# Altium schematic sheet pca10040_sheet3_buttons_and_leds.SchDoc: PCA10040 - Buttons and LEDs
size A4; Revision: 1.1.0; SheetNumber: 3; SheetTotal: 5; DrawnBy: KJP; ProjectNumber: 4397; PCBRevision: 0071KJP; DocumentSize: A4; PCAName: PCA10040; PCBNumber: 400150
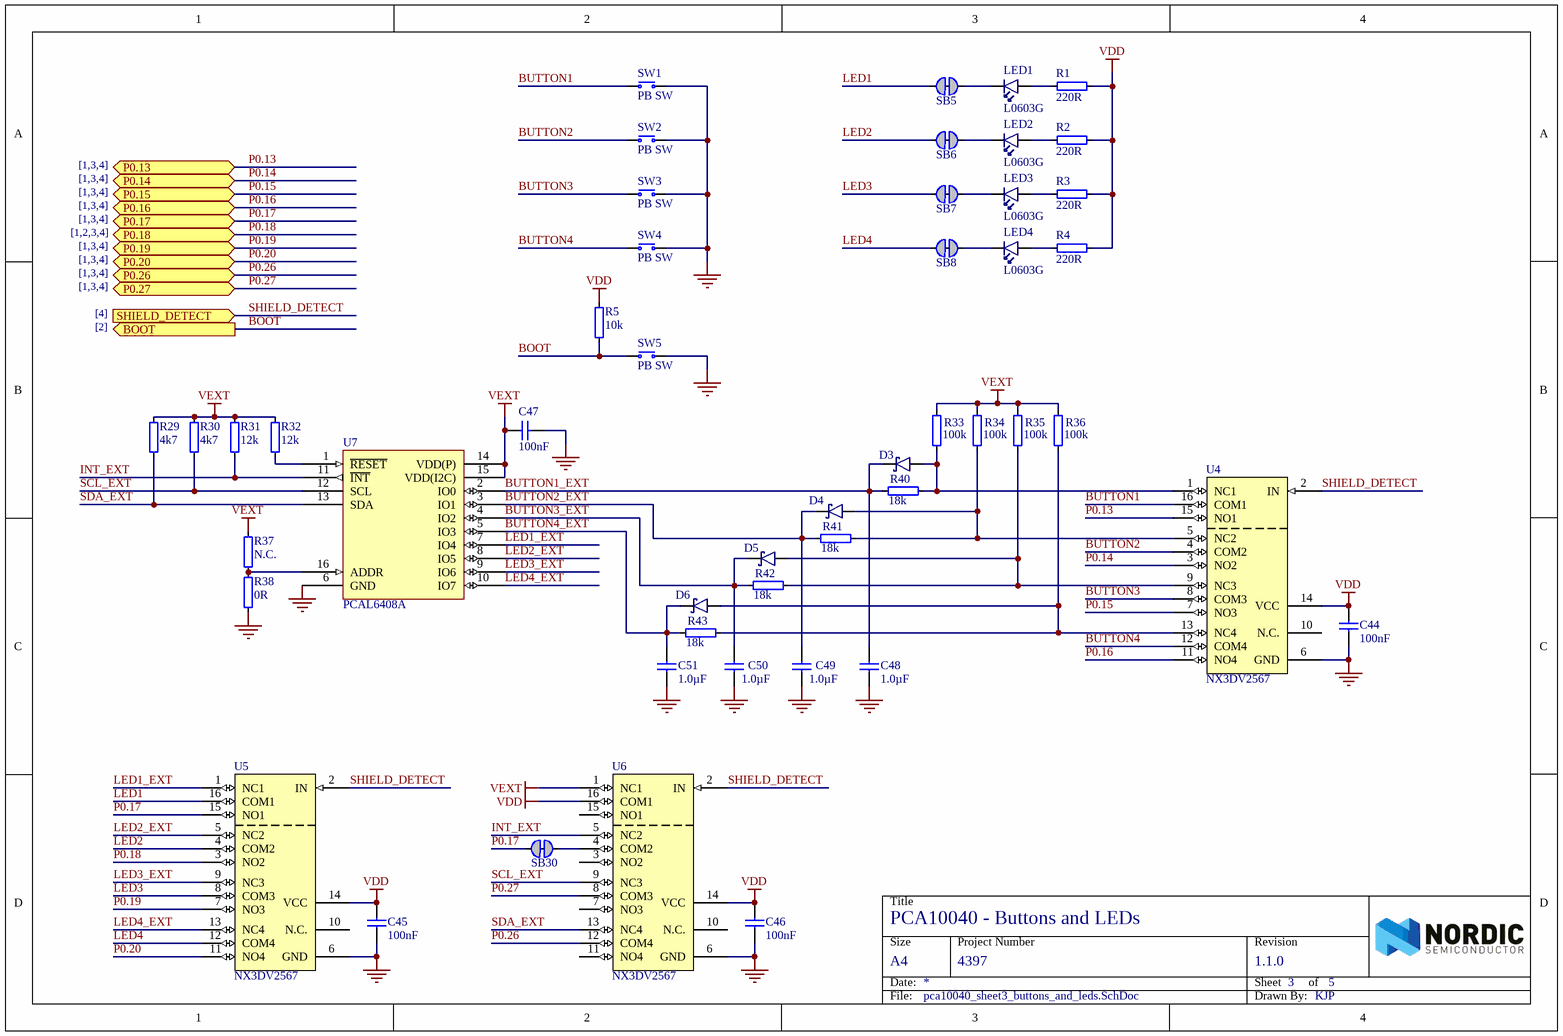
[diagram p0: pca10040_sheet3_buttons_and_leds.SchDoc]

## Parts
C44  100nF  [CAPC1005X04L]
C45  100nF  [CAPC1005X04L]
C46  100nF  [CAPC1005X04L]
C47  100nF  [CAPC1005X04L]
C48  1.0µF  [CAPC1005X04L]
C49  1.0µF  [CAPC1005X04L]
C50  1.0µF  [CAPC1005X04L]
C51  1.0µF  [CAPC1005X04L]
D3  1PS79SB30.115  [SOD-523]  (value not drawn)
D4  1PS79SB30.115  [SOD-523]  (value not drawn)
D5  1PS79SB30.115  [SOD-523]  (value not drawn)
D6  1PS79SB30.115  [SOD-523]  (value not drawn)
LED1  L0603G  [LED_0603_G]
LED2  L0603G  [LED_0603_G]
LED3  L0603G  [LED_0603_G]
LED4  L0603G  [LED_0603_G]
R1  220R  [RESC1005X04L]
R2  220R  [RESC1005X04L]
R3  220R  [RESC1005X04L]
R4  220R  [RESC1005X04L]
R5  10k  [RESC1005X04L]
R29  4k7  [RESC1005X04L]
R30  4k7  [RESC1005X04L]
R31  12k  [RESC1005X04L]
R32  12k  [RESC1005X04L]
R33  100k  [RESC1005X04L]
R34  100k  [RESC1005X04L]
R35  100k  [RESC1005X04L]
R36  100k  [RESC1005X04L]
R37  N.C.  [RESC1005X04L]
R38  0R  [RESC1005X04L]
R40  18k  [RESC1005X04L]
R41  18k  [RESC1005X04L]
R42  18k  [RESC1005X04L]
R43  18k  [RESC1005X04L]
SB5  Solderbridge  [Solderbridge_Shorted]  (value not drawn)  (net tie, no BOM)
SB6  Solderbridge  [Solderbridge_Shorted]  (value not drawn)  (net tie, no BOM)
SB7  Solderbridge  [Solderbridge_Shorted]  (value not drawn)  (net tie, no BOM)
SB8  Solderbridge  [Solderbridge_Shorted]  (value not drawn)  (net tie, no BOM)
SB30  Solderbridge  [Solderbridge_Shorted]  (value not drawn)  (net tie, no BOM)
SW1  PB SW  [ALPS_SKHUxxx010_WO_GND]
SW2  PB SW  [ALPS_SKHUxxx010_WO_GND]
SW3  PB SW  [ALPS_SKHUxxx010_WO_GND]
SW4  PB SW  [ALPS_SKHUxxx010_WO_GND]
SW5  PB SW  [ALPS_SKHUxxx010_WO_GND]
U4  NX3DV2567  [XQFN40P180X260X50-16N]
U5  NX3DV2567  [XQFN40P180X260X50-16N]
U6  NX3DV2567  [XQFN40P180X260X50-16N]
U7  PCAL6408A  [XQFN40P180X260X50-16N]

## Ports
BOOT (out), P0.13 (bidir), P0.14 (bidir), P0.15 (bidir), P0.16 (bidir), P0.17 (bidir), P0.18 (bidir), P0.19 (bidir), P0.20 (bidir), P0.26 (bidir), P0.27 (bidir), SHIELD_DETECT (in)

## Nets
GND: C44.1 C45.1 C46.1 C47.1 C48.2 C49.1 C50.1 C51.2 R38.1 SW1.2(COM) SW2.2(COM) SW3.2(COM) SW4.2(COM) SW5.2(COM) U4.6(GND) U5.6(GND) U6.6(GND) U7.6(GND)
VDD: C44.2 C45.2 C46.2 R1.2 R2.2 R3.2 R4.2 R5.2 U4.14(VCC) U5.14(VCC) U6.14(VCC) U6.16(COM1)
VEXT: C47.2 R29.2 R30.2 R31.2 R32.2 R33.2 R34.2 R35.2 R36.2 R37.2 U6.1(NC1) U7.14(VDD(P)) U7.15(VDD(I2C))
BOOT: R5.1 SW5.1(N.O) ; port BOOT
BUTTON1: SW1.1(N.O) U4.16(COM1)
BUTTON1_EXT: C48.1 D3.3(C) R40.1 U7.2(IO0)
BUTTON2: SW2.1(N.O) U4.4(COM2)
BUTTON2_EXT: C49.2 D4.3(C) R41.1 U7.3(IO1)
BUTTON3: SW3.1(N.O) U4.8(COM3)
BUTTON3_EXT: C50.2 D5.3(C) R42.1 U7.4(IO2)
BUTTON4: SW4.1(N.O) U4.12(COM4)
BUTTON4_EXT: C51.1 D6.3(C) R43.1 U7.5(IO3)
INT_EXT: R31.1 U6.5(NC2) U7.11(~{INT})
LED1: SB5.1 U5.16(COM1)
LED1_EXT: U5.1(NC1) U7.7(IO4)
LED2: SB6.1 U5.4(COM2)
LED2_EXT: U5.5(NC2) U7.8(IO5)
LED3: SB7.1 U5.8(COM3)
LED3_EXT: U5.9(NC3) U7.9(IO6)
LED4: SB8.1 U5.12(COM4)
LED4_EXT: U5.13(NC4) U7.10(IO7)
P0.13: U4.15(NO1) ; port P0.13
P0.14: U4.3(NO2) ; port P0.14
P0.15: U4.7(NO3) ; port P0.15
P0.16: U4.11(NO4) ; port P0.16
P0.17: SB30.1 U5.15(NO1) ; port P0.17
P0.18: U5.3(NO2) ; port P0.18
P0.19: U5.7(NO3) ; port P0.19
P0.20: U5.11(NO4) ; port P0.20
P0.26: U6.12(COM4) ; port P0.26
P0.27: U6.8(COM3) ; port P0.27
SCL_EXT: R30.1 U6.9(NC3) U7.12(SCL)
SDA_EXT: R29.1 U6.13(NC4) U7.13(SDA)
SHIELD_DETECT: U4.2(IN) U5.2(IN) U6.2(IN) ; port SHIELD_DETECT
NetD3_1: D3.1(A) R33.1 R40.2 U4.1(NC1)
NetD4_1: D4.1(A) R34.1 R41.2 U4.5(NC2)
NetD5_1: D5.1(A) R35.1 R42.2 U4.9(NC3)
NetD6_1: D6.1(A) R36.1 R43.2 U4.13(NC4)
NetLED1_1: LED1.1(C) SB5.2
NetLED1_2: LED1.2(A) R1.1
NetLED2_1: LED2.1(C) SB6.2
NetLED2_2: LED2.2(A) R2.1
NetLED3_1: LED3.1(C) SB7.2
NetLED3_2: LED3.2(A) R3.1
NetLED4_1: LED4.1(C) SB8.2
NetLED4_2: LED4.2(A) R4.1
NetR32_1: R32.1 U7.1(~{RESET})
NetR37_1: R37.1 R38.2 U7.16(ADDR)
NetSB30_2: SB30.2 U6.4(COM2)

Not connected (* = marked no-connect by the designer): U4 10(N.C.); U5 10(N.C.); U6 3(NO2) 7(NO3) 10(N.C.) 11(NO4) 15(NO1)

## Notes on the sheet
- [1,3,4]
- [1,2,3,4]
- [4]
- [2]

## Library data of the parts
C44-C47 = C0402-100n: Capacitor, X7R, ±10%; Note: 16V; Artikkelnr Noca: 20039200; Artikkelnr Simpro: N.A.
C48-C51 = C0402-1µ0: Capacitor, X5R, ±5%; Note: 6.3V; Artikkelnr Noca: 20039235; Artikkelnr Simpro: N.A.
D3-D6 = 1PS79SB30.115: Diode Schottky Vf=0.38, Vr=40V, If=200mA, Ir=500nA; Manufacturer: NXP; Artikkelnr Noca: N.A.
LED1-LED4 = EL19-21SYGC: LED 0603, EL19-21SYGC; Manufacturer: Everlight; Manufacturer Part Number: 19-21SYGC/S530-E1/TR8; Note: 16 mcd @ 20 mA; Artikkelnr Noca: 13019044; Artikkelnr Simpro: N.A.
R1-R4 = R0402-220: Resistor, ±1%, 0.063W; Note: Chip Res 1%; Artikkelnr Noca: 27049057; Artikkelnr Simpro: N.A.
R5 = R0402-10k: Resistor, ±1%, 0.063W; Note: Chip Res 1%; Artikkelnr Noca: 27049097; Artikkelnr Simpro: N.A.
R29 R30 = R0402-4k7: Resistor, ±1%, 0.063W; Note: Chip Res 1%; Artikkelnr Noca: 27049089; Artikkelnr Simpro: N.A.
R31 R32 = R0402-12k: Resistor, ±1%, 0.063W; Note: Chip Res 1%; Artikkelnr Noca: 27049099; Artikkelnr Simpro: N.A.
R33-R36 = R0402-100k: Resistor, ±1%, 0.063W; Note: Chip Res 1%; Artikkelnr Noca: 27049121; Artikkelnr Simpro: N.A.
R37 = R0402-N.C.: Not mounted; Note: Chip Res; Artikkelnr Noca: N.A.
R38 = R0402-0R: Resistor, ±5%, 0.063W; Note: Chip Res 5%; Artikkelnr Noca: 27049000; Artikkelnr Simpro: N.A.
R40-R43 = R0402-18k: Resistor, ±1%, 0.063W; Note: Chip Res 1%; Artikkelnr Noca: 27049103; Artikkelnr Simpro: N.A.
SB5-SB8 SB30 = Solderbridge Shorted: Shorted Solderbridge; Artikkelnr Noca: N.A.
SW1-SW5 = ALPS_SKHUALE010: ALPS - SKHUALE010 - Tactile Switch, SPNO, SMD, 6.5x6.2x2.5mm; 2nd source part number: 688-SKHUALE010; Artikkelnr Noca: 50019001; Artikkelnr Simpro: N.A.
U4-U6 = NX3DV2567GU: Low-ohmic four-pole double-throw analog switch; Manufacturer: NXP Semiconductors; 2nd source part number: 771-NX3DV2567GU115; Artikkelnr Noca: N.A.
U7 = PCAL6408AHK: 8-bit I2C-bus I/O expander with interrupt output; Manufacturer: NXP Semiconductors; 2nd source part number: 771-PCAL6408AHKX; Artikkelnr Noca: N.A.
